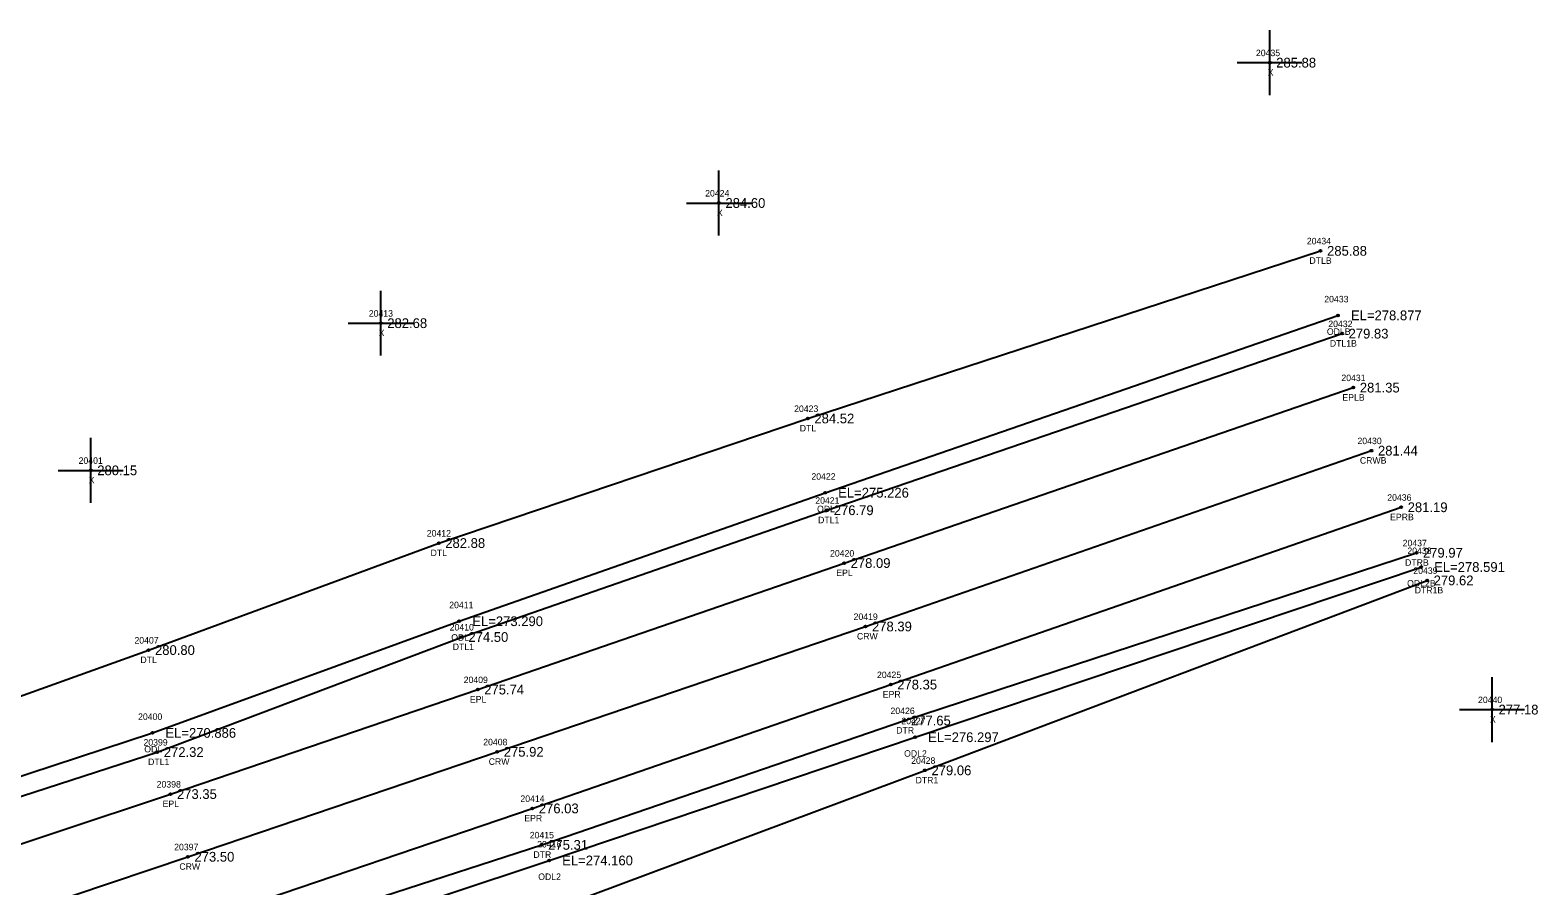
# Model space of a CAD drawing. Extents: x 2275563 to 2277161, y 1075719 to 1076412.
# Drawn here: x 2276928.6 to 2277160.5, y 1076194.1 to 1076325.8 of the extents above; entities that cross this region are included whole.
import ezdxf

# ---------------------------------------------------------------- set-up
doc = ezdxf.new("R2010")
doc.units = 0
for name, color, linetype in [('RD_DTM_BkLn1', 7, 'Continuous'), ('RD_EX_H2O', 7, 'Continuous'), ('RD_EX_H2O_txCode', 7, 'Continuous'), ('RD_EX_Misc', 7, 'Continuous'), ('RD_EX_Misc_txCode', 7, 'Continuous'), ('RD_EX_Road', 7, 'Continuous'), ('RD_EX_Road_txCode', 7, 'Continuous'), ('RD_EX_TX_H2O_ELEV', 7, 'Continuous'), ('RD_EX_TX_Misc_ELEV', 7, 'Continuous'), ('RD_EX_TX_Road_ELEV', 7, 'Continuous'), ('RD_HC_Survey_ELEV', 7, 'Continuous'), ('RD_HC_Survey_txCode', 7, 'Continuous'), ('RD_SMD_Locator', 7, 'Continuous')]:
    doc.layers.add(name, color=color, linetype=linetype)

msp = doc.modelspace()

# ---------------------------------------------------------------- linework, layer by layer
at = {"layer": 'RD_DTM_BkLn1'}
msp.add_lwpolyline([(2276380.47, 1076073.8), (2276432.36, 1076079.4), (2276487.41, 1076086.42), (2276535.62, 1076093.32), (2276578.15, 1076099.97), (2276622.03, 1076107.93), (2276668.51, 1076117.27), (2276714.2, 1076127.81), (2276762.94, 1076140.11), (2276806.88, 1076151.96), (2276854.94, 1076166.29), (2276899.73, 1076180.7), (2276952.88, 1076198.57), (2277000.46, 1076214.72), (2277057.1, 1076234.01), (2277134.93, 1076261.07)], dxfattribs=at)
at = {"layer": 'RD_EX_H2O'}
for points in [[(2276657.47, 1076152.34), (2276661.69, 1076153.68), (2276672.27, 1076150.14), (2276686.1, 1076148.32), (2276707.44, 1076155), (2276757.51, 1076168.89), (2276800.48, 1076181.68), (2276845.56, 1076196.09), (2276892.53, 1076210.89), (2276946.81, 1076230.38), (2276991.46, 1076246.85), (2277048.24, 1076266.02), (2277127.1, 1076291.82)], [(2276657.47, 1076152.34), (2276674.36, 1076145.77), (2276686.08, 1076143.69), (2276709.61, 1076149.05), (2276758.42, 1076158.57), (2276802.68, 1076170.14), (2276849.17, 1076183.99), (2276894.22, 1076200.15), (2276947.41, 1076217.63), (2276994.62, 1076234.82), (2277050.9, 1076254.6), (2277129.78, 1076281.89)], [(2276657.47, 1076152.34), (2276660.53, 1076148.68), (2276675.37, 1076140.15), (2276685.9, 1076140.33), (2276709.89, 1076145.63), (2276758.95, 1076156.3), (2276803.23, 1076167.04), (2276849.8, 1076180.23), (2276895.12, 1076197.46), (2276948.16, 1076214.68), (2276995.02, 1076232.39), (2277051.22, 1076251.9), (2277130.41, 1076279.08)], [(2276577.32, 1076064.99), (2276581.11, 1076068.71), (2276607.06, 1076074.47), (2276628.35, 1076084.13), (2276659.02, 1076095.85), (2276671.39, 1076099.39), (2276718.28, 1076111.88), (2276766.76, 1076124.15), (2276811.4, 1076137.27), (2276858.53, 1076152.16), (2276905.48, 1076167.47), (2276958.61, 1076184.59), (2277007.29, 1076200.4), (2277063.09, 1076219.53), (2277141.85, 1076245.35)], [(2276577.32, 1076064.99), (2276608.07, 1076069.56), (2276629.89, 1076080.39), (2276660.01, 1076094.12), (2276672.11, 1076097.43), (2276718.92, 1076109.66), (2276767.33, 1076122.4), (2276812.13, 1076135.39), (2276859.85, 1076149.89), (2276906.21, 1076164.41), (2276959.66, 1076181.81), (2277008.45, 1076198), (2277064.73, 1076216.97), (2277142.57, 1076243.16)], [(2276577.32, 1076064.99), (2276585.61, 1076060.77), (2276608.72, 1076065.79), (2276630.67, 1076076.21), (2276642.12, 1076079.44), (2276661.39, 1076087.16), (2276674.74, 1076089.6), (2276720.85, 1076101.92), (2276769.56, 1076115.83), (2276815.16, 1076127.06), (2276862.66, 1076139.65), (2276909.53, 1076154.75), (2276961.42, 1076172.61), (2277010.89, 1076191.18), (2277066.25, 1076211.87), (2277143.49, 1076241.1)]]:
    msp.add_lwpolyline(points, dxfattribs=at)
at = {"layer": 'RD_EX_Misc'}
for p, q in [((2277119.28, 1076315.78), (2277119.28, 1076325.78)), ((2277114.28, 1076320.78), (2277124.28, 1076320.78)), ((2277034.56, 1076294.18), (2277034.56, 1076304.18)), ((2277029.56, 1076299.18), (2277039.56, 1076299.18)), ((2276982.54, 1076275.69), (2276982.54, 1076285.69)), ((2276977.54, 1076280.69), (2276987.54, 1076280.69)), ((2276937.93, 1076253.04), (2276937.93, 1076263.04)), ((2276932.93, 1076258.04), (2276942.93, 1076258.04)), ((2277153.48, 1076216.22), (2277153.48, 1076226.22)), ((2277148.48, 1076221.22), (2277158.48, 1076221.22))]:
    msp.add_line(p, q, dxfattribs=at)
at = {"layer": 'RD_EX_Road'}
for points in [[(2276379.21, 1076084.39), (2276432.25, 1076089.28), (2276486.22, 1076095.98), (2276535.61, 1076103.32), (2276577.16, 1076110.11), (2276620.86, 1076117.78), (2276666.21, 1076126.9), (2276712, 1076137.22), (2276761.13, 1076149.72), (2276804.56, 1076161.71), (2276851.24, 1076175.53), (2276896.93, 1076190.53), (2276950.19, 1076208.22), (2276997.45, 1076224.3), (2277053.81, 1076243.77), (2277132.14, 1076270.77)], [(2276381.27, 1076063.04), (2276433.15, 1076069.16), (2276488.59, 1076076.23), (2276537.45, 1076083.34), (2276579.64, 1076090.09), (2276624.07, 1076098.24), (2276670.54, 1076107.46), (2276716.67, 1076118.09), (2276765.18, 1076130.28), (2276809.58, 1076142.25), (2276856.93, 1076156.58), (2276903.53, 1076171.63), (2276957.27, 1076189.46), (2277005.85, 1076206.01), (2277060.98, 1076225.07), (2277139.5, 1076252.36)]]:
    msp.add_lwpolyline(points, dxfattribs=at)
at = {"layer": 'RD_SMD_Locator'}
for centre in [(2277119.28, 1076320.78), (2277034.56, 1076299.18), (2277127.1, 1076291.82), (2277129.78, 1076281.89), (2276982.54, 1076280.69), (2277130.41, 1076279.08), (2277132.14, 1076270.77), (2277048.24, 1076266.02), (2277134.93, 1076261.07), (2276937.93, 1076258.04), (2277050.9, 1076254.6), (2277051.22, 1076251.9), (2277139.5, 1076252.36), (2276991.46, 1076246.85), (2277141.85, 1076245.35), (2277053.81, 1076243.77), (2277142.57, 1076243.16), (2277143.49, 1076241.1), (2276994.62, 1076234.82), (2277057.1, 1076234.01), (2276995.02, 1076232.39), (2276946.81, 1076230.38), (2276997.45, 1076224.3), (2277060.98, 1076225.07), (2277063.09, 1076219.53), (2277153.48, 1076221.22), (2276947.41, 1076217.63), (2277064.73, 1076216.97), (2276948.16, 1076214.68), (2277000.46, 1076214.72), (2277066.25, 1076211.87), (2276950.19, 1076208.22), (2277005.85, 1076206.01), (2276952.88, 1076198.57), (2277007.29, 1076200.4), (2277008.45, 1076198)]:
    msp.add_circle(centre, 0.15, dxfattribs=at)

# ---------------------------------------------------------------- texts
at = {"layer": 'RD_EX_H2O_txCode'}
for s, p in [('20434', (2277124.99, 1076292.82)), ('DTLB', (2277125.39, 1076289.82)), ('20433', (2277127.67, 1076283.89)), ('ODLB', (2277128.07, 1076278.89)), ('20432', (2277128.29, 1076280.08)), ('DTL1B', (2277128.53, 1076277.08)), ('20423', (2277046.12, 1076267.02)), ('DTL', (2277046.99, 1076264.02)), ('20422', (2277048.78, 1076256.6)), ('20421', (2277049.38, 1076252.9)), ('ODL', (2277049.65, 1076251.6)), ('DTL1', (2277049.81, 1076249.9)), ('20412', (2276989.62, 1076247.85)), ('20437', (2277139.73, 1076246.35)), ('DTL', (2276990.21, 1076244.85)), ('20438', (2277140.46, 1076245.16)), ('DTRB', (2277140.1, 1076243.35)), ('20439', (2277141.37, 1076242.1)), ('ODL2B', (2277140.41, 1076240.16)), ('DTR1B', (2277141.58, 1076239.1)), ('20411', (2276993.07, 1076236.82)), ('20410', (2276993.14, 1076233.39)), ('20407', (2276944.65, 1076231.38)), ('ODL', (2276993.38, 1076231.82)), ('DTL1', (2276993.61, 1076230.39)), ('DTL', (2276945.57, 1076228.38)), ('20426', (2277060.95, 1076220.53)), ('20400', (2276945.21, 1076219.63)), ('20427', (2277062.62, 1076218.97)), ('DTR', (2277061.83, 1076217.53)), ('20399', (2276946.04, 1076215.68)), ('ODL', (2276946.16, 1076214.63)), ('ODL2', (2277063.04, 1076213.97)), ('DTL1', (2276946.75, 1076212.68)), ('20428', (2277064.13, 1076212.87)), ('DTR1', (2277064.81, 1076209.87)), ('20415', (2277005.46, 1076201.4)), ('20416', (2277006.59, 1076200)), ('DTR', (2277006.02, 1076198.4)), ('ODL2', (2277006.76, 1076195))]:
    msp.add_text(s, height=1, dxfattribs=at).set_placement(p)
at = {"layer": 'RD_EX_Misc_txCode'}
for s, p in [('20435', (2277117.16, 1076321.78)), ('X', (2277118.97, 1076318.78)), ('20424', (2277032.44, 1076300.18)), ('X', (2277034.25, 1076297.18)), ('20413', (2276980.7, 1076281.69)), ('X', (2276982.22, 1076278.69)), ('20401', (2276936.06, 1076259.04)), ('X', (2276937.61, 1076256.04)), ('20440', (2277151.32, 1076222.22)), ('X', (2277153.16, 1076219.22))]:
    msp.add_text(s, height=1, dxfattribs=at).set_placement(p)
at = {"layer": 'RD_EX_Road_txCode'}
for s, p in [('20431', (2277130.3, 1076271.77)), ('EPLB', (2277130.46, 1076268.77)), ('20436', (2277137.36, 1076253.36)), ('EPRB', (2277137.8, 1076250.36)), ('20420', (2277051.65, 1076244.77)), ('EPL', (2277052.61, 1076241.77)), ('20409', (2276995.29, 1076225.3)), ('20425', (2277058.87, 1076226.07)), ('EPR', (2277059.76, 1076223.07)), ('EPL', (2276996.25, 1076222.3)), ('20398', (2276948.07, 1076209.22)), ('20414', (2277004.02, 1076207.01)), ('EPL', (2276948.98, 1076206.22)), ('EPR', (2277004.62, 1076204.01))]:
    msp.add_text(s, height=1, dxfattribs=at).set_placement(p)
at = {"layer": 'RD_EX_TX_H2O_ELEV'}
for s, p in [('285.88', (2277128.1, 1076291.07)), ('EL=278.877', (2277131.78, 1076281.14)), ('279.83', (2277131.41, 1076278.33)), ('284.52', (2277049.24, 1076265.27)), ('EL=275.226', (2277052.9, 1076253.85)), ('276.79', (2277052.22, 1076251.15)), ('282.88', (2276992.46, 1076246.1)), ('279.97', (2277142.85, 1076244.6)), ('EL=278.591', (2277144.57, 1076242.41)), ('279.62', (2277144.49, 1076240.35)), ('EL=273.290', (2276996.62, 1076234.07)), ('274.50', (2276996.02, 1076231.64)), ('280.80', (2276947.81, 1076229.63)), ('277.65', (2277064.09, 1076218.78)), ('EL=270.886', (2276949.41, 1076216.88)), ('EL=276.297', (2277066.73, 1076216.22)), ('272.32', (2276949.16, 1076213.93)), ('279.06', (2277067.25, 1076211.12)), ('275.31', (2277008.29, 1076199.65)), ('EL=274.160', (2277010.45, 1076197.25))]:
    msp.add_text(s, height=1.5, dxfattribs=at).set_placement(p)
at = {"layer": 'RD_EX_TX_Misc_ELEV'}
for s, p in [('285.88', (2277120.28, 1076320.03)), ('284.60', (2277035.56, 1076298.43)), ('282.68', (2276983.54, 1076279.94)), ('280.15', (2276938.93, 1076257.29)), ('277.18', (2277154.48, 1076220.47))]:
    msp.add_text(s, height=1.5, dxfattribs=at).set_placement(p)
at = {"layer": 'RD_EX_TX_Road_ELEV'}
for s, p in [('281.35', (2277133.14, 1076270.02)), ('281.19', (2277140.5, 1076251.61)), ('278.09', (2277054.81, 1076243.02)), ('275.74', (2276998.45, 1076223.55)), ('278.35', (2277061.98, 1076224.32)), ('273.35', (2276951.19, 1076207.47)), ('276.03', (2277006.85, 1076205.26))]:
    msp.add_text(s, height=1.5, dxfattribs=at).set_placement(p)
at = {"layer": 'RD_HC_Survey_ELEV'}
for s, p in [('281.44', (2277135.93, 1076260.32)), ('278.39', (2277058.1, 1076233.26)), ('275.92', (2277001.46, 1076213.97)), ('273.50', (2276953.88, 1076197.82))]:
    msp.add_text(s, height=1.5, dxfattribs=at).set_placement(p)
at = {"layer": 'RD_HC_Survey_txCode'}
for s, p in [('20430', (2277132.78, 1076262.07)), ('CRWB', (2277133.15, 1076259.07)), ('20419', (2277055.27, 1076235.01)), ('CRW', (2277055.79, 1076232.01)), ('20408', (2276998.3, 1076215.72)), ('CRW', (2276999.14, 1076212.72)), ('20397', (2276950.76, 1076199.57)), ('CRW', (2276951.56, 1076196.57))]:
    msp.add_text(s, height=1, dxfattribs=at).set_placement(p)

doc.saveas('drawing.dxf')
